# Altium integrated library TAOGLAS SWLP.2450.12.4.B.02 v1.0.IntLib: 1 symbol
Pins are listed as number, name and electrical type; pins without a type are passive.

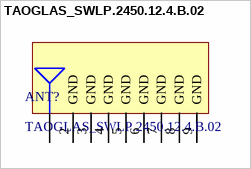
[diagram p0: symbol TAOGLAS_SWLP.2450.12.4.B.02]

## TAOGLAS_SWLP.2450.12.4.B.02
designator ANT?
WiFi, Zigbee, ISM 2.4 - 2.5GHz Wi-Fi Patch Antenna; ComponentLibStatus: Created; Temp_High: +85C; Temp_Low: -40C
footprint SWLP.2450.12.4.B.02 (WiFi, Zigbee, ISM 2.4 - 2.5GHz Wi-Fi Patch Antenna)
pins: 1 RF, 2 GND, 3 GND, 4 GND, 5 GND, 6 GND, 7 GND, 8 GND, 9 GND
